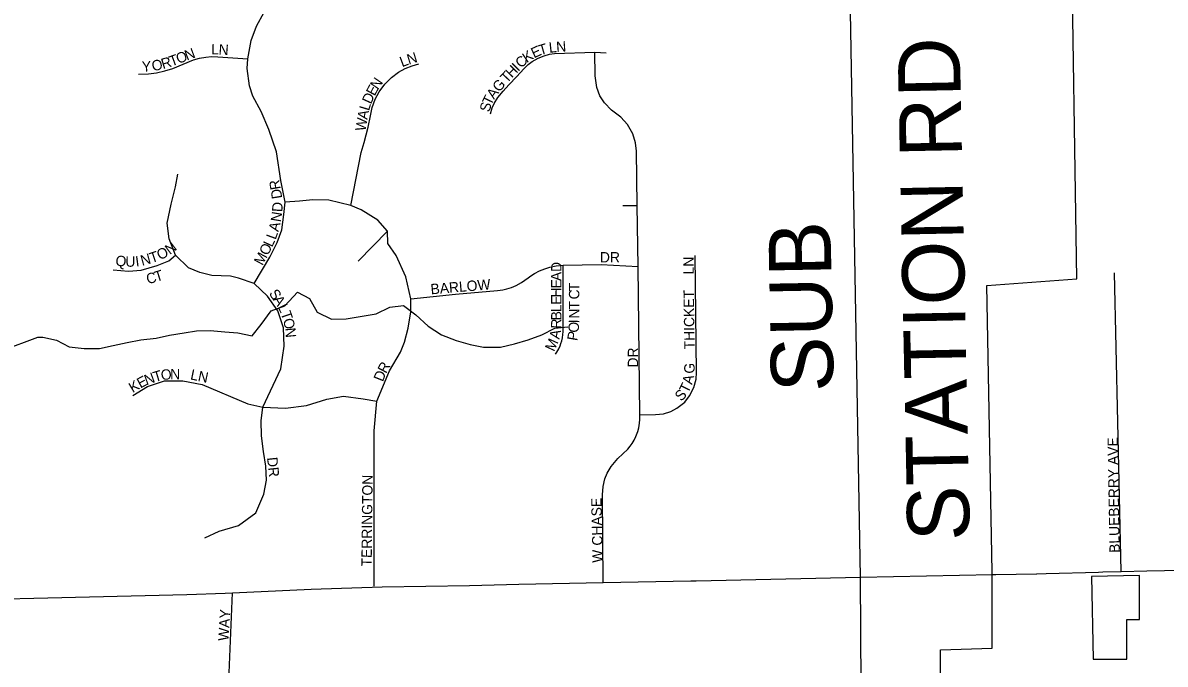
# Model space of a CAD drawing. Extents: x 1985906 to 2277390, y 930619 to 1324581.
# Drawn here: x 2140400 to 2145909, y 1179804 to 1182896 of the extents above; entities that cross this region are included whole.
import ezdxf

# ---------------------------------------------------------------- set-up
doc = ezdxf.new("R2010")
doc.units = 0
for name, color, linetype in [('GM_X_City_Street', 7, 'Continuous'), ('GM_X_City_Street_Text', 7, 'Continuous'), ('GM_X_Corporation', 7, 'Continuous'), ('GM_X_County_Road', 7, 'Continuous'), ('GM_X_County_Road_Text', 7, 'Continuous'), ('GM_X_Minor_River', 7, 'Continuous'), ('GM_X_State_Route', 7, 'Continuous'), ('GM_X_Township_Road', 7, 'Continuous'), ('GM_X_Township_Subdivision', 7, 'Continuous'), ('GM_X_Township_Subdivision_Text', 7, 'Continuous')]:
    doc.layers.add(name, color=color, linetype=linetype)

msp = doc.modelspace()

# ---------------------------------------------------------------- linework, layer by layer
at = {"layer": 'GM_X_City_Street'}
msp.add_lwpolyline([(2145696.3, 1180250.6), (2145665.4, 1181690.5)], dxfattribs=at)
at = {"layer": 'GM_X_Corporation'}
msp.add_lwpolyline([(2146361.4, 1177260), (2145712.7, 1177262.7), (2145073.4, 1177262.8), (2145073.9, 1179033.9), (2144825.3, 1179402.6), (2144825.5, 1179872.8), (2145074.1, 1179881.5), (2145074.2, 1180249.6), (2145049.1, 1181629.2), (2145483.6, 1181661.4), (2145455.2, 1183439.8), (2144378.7, 1183443.5), (2144355.8, 1185446.4), (2145105.1, 1185449.7), (2145102.2, 1185591.2), (2145978.7, 1185600.1)], dxfattribs=at)
msp.add_lwpolyline([(2145554.5, 1180226.2), (2145561.8, 1179828.6), (2145723.9, 1179828.6), (2145724, 1180019.7), (2145785, 1180019.7), (2145785.1, 1180231.3)], close=True, dxfattribs=at)
at = {"layer": 'GM_X_County_Road'}
msp.add_lwpolyline([(2144439.9, 1180223.6), (2144384.5, 1183313.6)], dxfattribs=at)
at = {"layer": 'GM_X_Minor_River'}
for points in [[(2140472.7, 1181379.7), (2140496.1, 1181379.7), (2140562.1, 1181365.7), (2140624.1, 1181333.7), (2140696.1, 1181325.8), (2140770.1, 1181325.8), (2140836, 1181339.9), (2140904, 1181354), (2140970, 1181368.1), (2141043.9, 1181376.2), (2141107.9, 1181390.3), (2141177.9, 1181400.4), (2141237.8, 1181410.4), (2141303.8, 1181412.5), (2141373.8, 1181406.6), (2141437.8, 1181400.6), (2141505.8, 1181386.6), (2141549.7, 1181440.8), (2141597.6, 1181507), (2141663.6, 1181531.1), (2141725.5, 1181597.3), (2141783.5, 1181567.3), (2141819.5, 1181501.2), (2141889.6, 1181467.2), (2141959.5, 1181469.2), (2142103.5, 1181493.4), (2142169.4, 1181525.6), (2142235.4, 1181533.6), (2142295.4, 1181487.6), (2142355.4, 1181433.5), (2142419.4, 1181391.5), (2142489.4, 1181363.5), (2142557.4, 1181345.5), (2142621.4, 1181331.5), (2142703.4, 1181331.6), (2142771.3, 1181347.7), (2142837.3, 1181367.8), (2142903.3, 1181391.9), (2142965.2, 1181424.1), (2143029.2, 1181430.1)], [(2140300.6, 1181315.6), (2140472.8, 1181379.7)]]:
    msp.add_lwpolyline(points, dxfattribs=at)
at = {"layer": 'GM_X_State_Route'}
for points in [[(2143647.5, 1180205.5), (2144439.9, 1180223.6), (2145077.1, 1180235.9)], [(2145077.1, 1180235.9), (2145092.5, 1180236.2), (2145289.4, 1180239.9), (2145289.5, 1180239.9)], [(2145289.5, 1180239.9), (2145335.2, 1180240.8), (2145588.1, 1180247.7), (2145608.1, 1180248.2)], [(2145608.1, 1180248.2), (2145696.3, 1180250.6), (2145820.5, 1180253.3)], [(2145820.5, 1180253.3), (2145990.7, 1180256.9), (2146086, 1180258)], [(2141376.4, 1180146.7), (2141411.8, 1180148), (2141791.3, 1180164.6), (2142132.5, 1180176), (2142554.4, 1180183.2), (2142792.6, 1180189.3), (2143198.9, 1180197), (2143621.6, 1180204.9), (2143647.5, 1180205.5)], [(2139580.5, 1180100.5), (2141190.5, 1180139.8), (2141376.4, 1180146.7)]]:
    msp.add_lwpolyline(points, dxfattribs=at)
at = {"layer": 'GM_X_Township_Road'}
msp.add_lwpolyline([(2144494.5, 1172175.5), (2144487.3, 1173938.3), (2144467.5, 1175109.3), (2144465.5, 1176033.7), (2144439.9, 1180223.6)], dxfattribs=at)
at = {"layer": 'GM_X_Township_Subdivision'}
for points in [[(2141516, 1181638.7), (2141590.7, 1181766.1), (2141626.8, 1181836.3), (2141648.8, 1181898.4), (2141658.8, 1181972.5), (2141664.8, 1182030.7), (2141644.8, 1182134.9), (2141622.8, 1182273.2), (2141586.7, 1182381.4), (2141549.2, 1182468.9), (2141510, 1182541.9), (2141494, 1182591.7), (2141481.5, 1182675.4), (2141485.1, 1182721.7), (2141501.1, 1182810.7), (2141527.8, 1182880.1), (2141563.4, 1182947.8), (2141591.9, 1183013.7), (2141607.9, 1183088.5), (2141622.2, 1183172.2), (2141631.9, 1183214.8)], [(2140958.6, 1182647.9), (2141005.7, 1182650), (2141045.4, 1182655.3), (2141084.6, 1182663.8), (2141122.9, 1182675.4), (2141223.2, 1182717.5), (2141252.9, 1182725.8), (2141283, 1182730.9), (2141310.3, 1182732.9), (2141340.5, 1182732.2), (2141485.1, 1182721.7)], [(2142656.3, 1182456.7), (2142664.3, 1182485.7), (2142673, 1182506.3), (2142690.7, 1182535.6), (2142716.4, 1182565.6), (2142744.6, 1182596.3), (2142782.5, 1182637.6), (2142816.3, 1182674.5), (2142837, 1182694.4), (2142856.6, 1182709.2), (2142885.8, 1182726.1), (2142913.8, 1182737.4), (2142940.7, 1182744.5), (2142964.9, 1182748), (2143158.5, 1182754.7), (2143214.1, 1182751.9)], [(2143198.9, 1180197), (2143195.4, 1180620.9), (2143198.4, 1180660.7), (2143207.2, 1180697.2), (2143218.1, 1180724.7), (2143236.7, 1180757.5), (2143269, 1180795.8), (2143317.6, 1180840.5), (2143329.3, 1180854.6), (2143338.2, 1180867.1), (2143348.5, 1180884.3), (2143356.5, 1180900.8), (2143366, 1180925.8), (2143370.6, 1180943.3), (2143374.5, 1180965.3), (2143376, 1180983), (2143376.2, 1181006.2), (2143367.2, 1181720.5), (2143363.2, 1182015.8), (2143359.7, 1182277.2), (2143355.6, 1182316.9), (2143341.9, 1182361), (2143315.7, 1182406.4), (2143283.6, 1182440.8), (2143238.4, 1182474.6), (2143205, 1182509.6), (2143183.6, 1182543.8), (2143168.2, 1182583.5), (2143160, 1182640.2), (2143158.5, 1182754.7)], [(2141981.5, 1182014.6), (2142032.1, 1182270.3), (2142046.6, 1182319.3), (2142065.2, 1182393.3), (2142076.2, 1182447.1), (2142084.7, 1182487), (2142099.6, 1182527.8), (2142118.8, 1182563.8), (2142145.8, 1182600.4), (2142178.2, 1182632.7), (2142211.6, 1182657.4), (2142243.8, 1182675.4), (2142277.1, 1182688.9), (2142310.1, 1182698)], [(2141277.3, 1180413.3), (2141347.8, 1180444.4), (2141439.6, 1180472.3), (2141523.2, 1180532.9), (2141562.6, 1180623.1), (2141575.7, 1180690.4), (2141572.5, 1180757.6), (2141561, 1180829.7), (2141551.1, 1180905.2), (2141549.5, 1180977.3), (2141557.6, 1181042.8), (2141644.8, 1181227), (2141660.8, 1181337.3), (2141656.8, 1181425.4), (2141630.8, 1181507.6), (2141580.7, 1181577.8), (2141516, 1181638.7), (2141440.5, 1181665.2), (2141401.4, 1181673.6), (2141312, 1181677.8), (2141253.3, 1181691.8), (2141198.8, 1181714.1), (2141137.3, 1181775.6), (2141105.2, 1181853.9), (2141096.8, 1181930.7), (2141115, 1182021.5), (2141137.3, 1182105.4), (2141147.1, 1182166.9)], [(2142094, 1180389.5), (2142094.3, 1180928.1), (2142107.9, 1181072.4), (2142168.2, 1181217.2), (2142221.5, 1181307.2), (2142241.1, 1181356), (2142259.2, 1181424), (2142271.3, 1181502.8), (2142271.1, 1181564.8), (2142246.5, 1181671.7), (2142200.5, 1181774.7), (2142160.9, 1181832), (2142158.6, 1181892), (2142113, 1181944.7), (2142031.6, 1181995), (2141981.5, 1182014.6), (2141875.8, 1182040.6), (2141799.1, 1182043), (2141734.4, 1182035.8), (2141664.8, 1182030.7)], [(2143293.3, 1182015), (2143363.2, 1182015.8)], [(2142017.6, 1181746.1), (2142158.6, 1181892)], [(2140835.5, 1181704.3), (2140909.6, 1181698.8), (2140971, 1181703), (2141047.9, 1181725.3), (2141103.8, 1181747.7), (2141137.3, 1181775.6)], [(2142271.1, 1181564.8), (2142486.3, 1181587.8), (2142688.6, 1181605.5), (2142714.5, 1181609.2), (2142734.2, 1181613.6), (2142756.7, 1181620.5), (2142779.1, 1181629.7), (2142804.9, 1181643.1), (2142837.8, 1181665.8), (2142850.6, 1181675.4), (2142868.4, 1181687.1), (2142891.4, 1181699.5), (2142917.1, 1181710.3), (2142942.3, 1181718.1), (2142972.2, 1181724.2), (2143006, 1181727), (2143189.5, 1181729.9), (2143367.2, 1181720.5)], [(2142969.2, 1181298.6), (2142975.1, 1181307.4), (2142980.1, 1181315.7), (2142984.8, 1181324.5), (2142991.2, 1181338.4), (2142995.4, 1181349.7), (2142999.5, 1181363.2), (2143002.6, 1181377.2), (2143004.9, 1181392.4), (2143005.9, 1181405.3), (2143006, 1181419), (2143006, 1181727)], [(2143376.2, 1181006.2), (2143451.8, 1181007.2), (2143489.8, 1181011.3), (2143524.7, 1181021.9), (2143554.6, 1181037.2), (2143592.5, 1181067.6), (2143616, 1181096.7), (2143636.9, 1181137.9), (2143647.1, 1181177.7), (2143649.2, 1181209.7), (2143641.9, 1181774.7)], [(2140931.3, 1181098.6), (2141001.9, 1181142.9), (2141083.8, 1181169.1), (2141172.4, 1181169.1), (2141265.8, 1181152.8), (2141485.5, 1181059.3), (2141557.6, 1181042.8), (2141667.3, 1181037.2), (2141767.5, 1181050.7), (2141866.9, 1181082.1), (2141947, 1181095.5), (2142041.2, 1181083.6), (2142107.9, 1181072.4)], [(2142093.9, 1180179.3), (2142094, 1180389.5)], [(2141383.9, 1179150.2), (2141388, 1179309.5), (2141394.2, 1179724.1), (2141411.8, 1180148)]]:
    msp.add_lwpolyline(points, dxfattribs=at)

# ---------------------------------------------------------------- texts
at = {"layer": 'GM_X_City_Street_Text'}
msp.add_text('BLUEBERRY AVE', height=50, rotation=90.9977, dxfattribs=at).set_placement((2145690.7, 1180340.7))
at = {"layer": 'GM_X_County_Road_Text'}
for s, rotation, p in [('STATION RD', 91.1623, (2144967.2, 1180399.8)), ('SUB', 91.0603, (2144310.3, 1181117.4))]:
    msp.add_text(s, height=300, rotation=rotation, dxfattribs=at).set_placement(p)
at = {"layer": 'GM_X_Township_Subdivision_Text'}
for s, rotation, p in [('N', 20.8727, (2141191.6, 1182712.9)), ('L', 358.9345, (2141308.6, 1182743.8)), ('N', 356.0841, (2141343.2, 1182743.2)), ('E', 24.8057, (2142865.2, 1182724.2)), ('T', 16.5082, (2142895.4, 1182738.3)), ('L', 5.8302, (2142939.5, 1182751)), ('N', 4.1557, (2142974.1, 1182754.6)), ('O', 10.5908, (2141026.9, 1182662.8)), ('R', 16.9881, (2141076, 1182672.4)), ('T', 20.2583, (2141116.9, 1182684.9)), ('O', 20.7722, (2141150.4, 1182697.3)), ('L', 20.7767, (2142229.2, 1182681.5)), ('N', 17.0111, (2142261.3, 1182693.7)), ('C', 44.7081, (2142804.2, 1182674.4)), ('K', 33.7689, (2142830.4, 1182700.7)), ('Y', 2.2303, (2140975, 1182660.2)), ('T', 47.164, (2142734.6, 1182601.8)), ('H', 45.7882, (2142758.3, 1182627.4)), ('I', 45.5256, (2142789, 1182658.9)), ('N', 55.4431, (2142112.4, 1182570)), ('G', 49.4556, (2142697.7, 1182558.8)), ('D', 65.547, (2142079, 1182500.8)), ('E', 62.384, (2142096.9, 1182540.1)), ('T', 64.4615, (2142658.6, 1182494.3)), ('A', 54.0787, (2142672.5, 1182524)), ('L', 73.0077, (2142069.3, 1182468.7)), ('S', 74.9366, (2142650.3, 1182462.6)), ('W', 80.405, (2142052, 1182370.7)), ('A', 79.2729, (2142061.5, 1182426.9)), ('R', 99.7841, (2141644.6, 1182095.1)), ('D', 98.926, (2141651.6, 1182050.9)), ('D', 87.0991, (2141651.8, 1181982.6)), ('N', 80.8531, (2141644.1, 1181933.2)), ('A', 76.0766, (2141632.6, 1181886.1)), ('N', 37.2344, (2141109.4, 1181775.8)), ('L', 64.9175, (2141602.2, 1181811.1)), ('L', 70.0693, (2141619, 1181847.5)), ('N', 15.1161, (2140975.3, 1181724.3)), ('T', 18.1877, (2141020.6, 1181736.6)), ('O', 26.7314, (2141061.6, 1181750.7)), ('M', 61.6265, (2141555.8, 1181722.6)), ('O', 63.1831, (2141581.6, 1181770.4)), ('DR', 0, (2143183.3, 1181740.6)), ('Q', 352.856, (2140844.8, 1181726)), ('U', 359.4071, (2140894.7, 1181720.1)), ('I', 7.3869, (2140946.3, 1181720.1)), ('D', 89.9928, (2142997.9, 1181694.7)), ('LN', 90, (2143635.9, 1181682.8)), ('C', 15.0315, (2141003, 1181635.2)), ('T', 17.6473, (2141043.7, 1181646.2)), ('A', 89.9928, (2142997.9, 1181650.7)), ('BARLOW', 4.7648, (2142368.5, 1181586.6)), ('E', 89.9956, (2142997.9, 1181615.5)), ('H', 89.9928, (2142997.9, 1181571.5)), ('T', 89.9956, (2143083.9, 1181602)), ('S', 303.4476, (2141585.1, 1181591.3)), ('A', 303.4739, (2141604.5, 1181561.9)), ('E', 89.9956, (2142997.9, 1181536.3)), ('C', 89.994, (2143083.9, 1181562.4)), ('THICKET', 90.833, (2143640.3, 1181321.9)), ('L', 296.3818, (2141627.9, 1181526.6)), ('T', 289.0051, (2141642.9, 1181496.6)), ('B', 89.9466, (2142997.8, 1181461.5)), ('L', 89.9956, (2142997.9, 1181501.1)), ('N', 89.7337, (2143083.7, 1181469.8)), ('T', 89.9707, (2143083.9, 1181514)), ('O', 284.5823, (2141654.1, 1181464.3)), ('R', 89.0555, (2142997.2, 1181421)), ('O', 86.6489, (2143080.4, 1181400.9)), ('I', 88.2965, (2143083, 1181446.4)), ('N', 275.2973, (2141664.8, 1181423.8)), ('A', 78.4966, (2142987.3, 1181367.9)), ('P', 80.1693, (2143073.7, 1181360.1)), ('M', 65.5123, (2142961.6, 1181308.1)), ('DR', 90, (2143367.5, 1181234)), ('N', 0.2623, (2141111, 1181177.2)), ('R', 61.7946, (2142152, 1181201.9)), ('G', 88.9569, (2143639.4, 1181204.1)), ('K', 30.6938, (2140930, 1181110.1)), ('E', 28.484, (2140967.4, 1181132.3)), ('N', 19.8449, (2140996.5, 1181148.2)), ('T', 16.3957, (2141037.1, 1181162.9)), ('O', 6.3957, (2141068.6, 1181172.4)), ('LN', 348.1096, (2141205.3, 1181177.2)), ('D', 67.8861, (2142136, 1181162.4)), ('A', 76.3769, (2143627.5, 1181149.4)), ('S', 48.5185, (2143576.6, 1181068.1)), ('T', 64.0544, (2143608.1, 1181106.7)), ('DR', 276.0216, (2141577.8, 1180799.5)), ('TERRINGTON', 89.3643, (2142082.7, 1180274.7)), ('CHASE', 91.2448, (2143195.9, 1180375.8)), ('W', 90, (2143195.9, 1180292.4)), ('WAY', 86.5338, (2141391.9, 1179914.6))]:
    msp.add_text(s, height=50, rotation=rotation, dxfattribs=at).set_placement(p)

doc.saveas('drawing.dxf')
